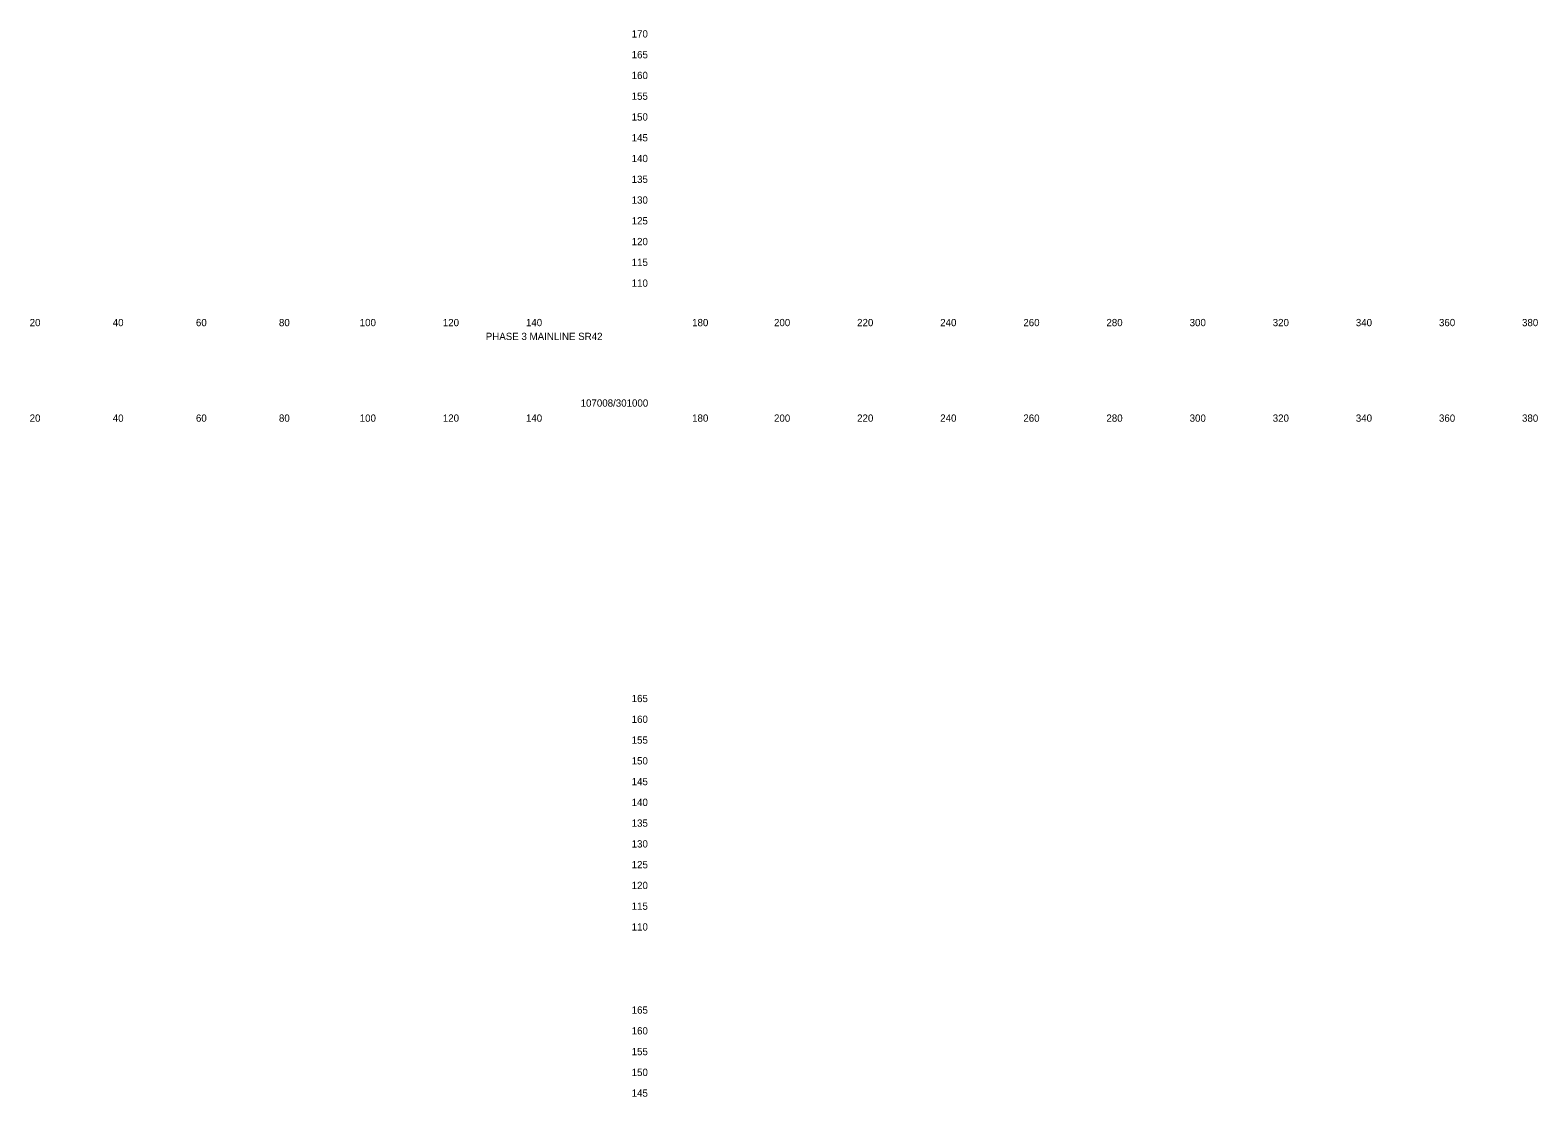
# Model space of a CAD drawing. Extents: x 21281 to 22024, y 6472 to 15198.
# Drawn here: x 21661.4 to 22024.2, y 9739.8 to 9996.6 of the extents above; entities that cross this region are included whole.
import ezdxf

# ---------------------------------------------------------------- set-up
doc = ezdxf.new("R2010")
doc.units = 0
doc.layers.add('Draft_XS_Grid', color=7, linetype='Continuous')
doc.layers.add('Draft_XS_Text', color=7, linetype='Continuous')

msp = doc.modelspace()

# ---------------------------------------------------------------- texts
at = {"layer": 'Draft_XS_Grid'}
for s, p in [('  170  ', (21804.84, 9994.84)), ('  165  ', (21804.84, 9989.84)), ('  160  ', (21804.84, 9984.84)), ('  155  ', (21804.84, 9979.84)), ('  150  ', (21804.84, 9974.84)), ('  145  ', (21804.84, 9969.84)), ('  140  ', (21804.84, 9964.84)), ('  135  ', (21804.84, 9959.84)), ('  130  ', (21804.84, 9954.84)), ('  125  ', (21804.84, 9949.84)), ('  120  ', (21804.84, 9944.84)), ('  115  ', (21804.84, 9939.84)), ('  110  ', (21804.84, 9934.84)), ('  165  ', (21804.84, 9834.84)), ('  160  ', (21804.84, 9829.84)), ('  155  ', (21804.84, 9824.84)), ('  150  ', (21804.84, 9819.84)), ('  145  ', (21804.84, 9814.84)), ('  140  ', (21804.84, 9809.84)), ('  135  ', (21804.84, 9804.84)), ('  130  ', (21804.84, 9799.84)), ('  125  ', (21804.84, 9794.84)), ('  120  ', (21804.84, 9789.84)), ('  115  ', (21804.84, 9784.84)), ('  110  ', (21804.84, 9779.84)), ('  165  ', (21804.84, 9759.84)), ('  160  ', (21804.84, 9754.84)), ('  155  ', (21804.84, 9749.84)), ('  150  ', (21804.84, 9744.84)), ('  145  ', (21804.84, 9739.84))]:
    msp.add_text(s, height=1.75, dxfattribs=at).set_placement(p)
at = {"layer": 'Draft_XS_Text'}
for s, p in [('  20  ', (21659.95, 9925.34)), ('  40  ', (21679.95, 9925.34)), ('  60  ', (21699.97, 9925.34)), ('  80  ', (21719.95, 9925.34)), ('  100  ', (21739.39, 9925.34)), ('  120  ', (21759.39, 9925.34)), ('  140  ', (21779.39, 9925.34)), ('  180  ', (21819.39, 9925.34)), ('  200  ', (21839.1, 9925.34)), ('  220  ', (21859.1, 9925.34)), ('  240  ', (21879.1, 9925.34)), ('  260  ', (21899.11, 9925.34)), ('  280  ', (21919.1, 9925.34)), ('  300  ', (21939.13, 9925.34)), ('  320  ', (21959.13, 9925.34)), ('  340  ', (21979.13, 9925.34)), ('  360  ', (21999.14, 9925.34)), ('  380  ', (22019.13, 9925.34)), ('PHASE 3 MAINLINE SR42', (21771.03, 9922.01)), ('107008/301000', (21793.86, 9905.97)), ('  20  ', (21659.95, 9902.34)), ('  40  ', (21679.95, 9902.34)), ('  60  ', (21699.97, 9902.34)), ('  80  ', (21719.95, 9902.34)), ('  100  ', (21739.39, 9902.34)), ('  120  ', (21759.39, 9902.34)), ('  140  ', (21779.39, 9902.34)), ('  180  ', (21819.39, 9902.34)), ('  200  ', (21839.1, 9902.34)), ('  220  ', (21859.1, 9902.34)), ('  240  ', (21879.1, 9902.34)), ('  260  ', (21899.11, 9902.34)), ('  280  ', (21919.1, 9902.34)), ('  300  ', (21939.13, 9902.34)), ('  320  ', (21959.13, 9902.34)), ('  340  ', (21979.13, 9902.34)), ('  360  ', (21999.14, 9902.34)), ('  380  ', (22019.13, 9902.34))]:
    msp.add_text(s, height=1.75, dxfattribs=at).set_placement(p)

doc.saveas('drawing.dxf')
